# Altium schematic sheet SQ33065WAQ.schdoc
size 127 x 101 mm
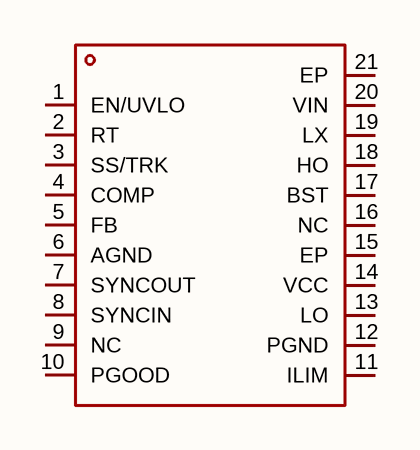
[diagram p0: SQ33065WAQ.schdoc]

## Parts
U?  sq33065waq  [TQFN-20_L4.5-W3.5-P0.50-TL-EP2.7]  (value not drawn)

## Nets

Not connected (* = marked no-connect by the designer): U? 1(EN/UVLO) 2(RT) 3(SS/TRK) 4(COMP) 5(FB) 6(AGND) 7(SYNCOUT) 8(SYNCIN) 9(NC) 10(PGOOD) 11(ILIM) 12(PGND) 13(LO) 14(VCC) 15(EP) 16(NC) 17(BST) 18(HO) 19(LX) 20(VIN) 21(EP)

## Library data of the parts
U? = sq33065waq: 功能类型:降压型;工作电压:6V~75V;输出电压:-;输出电流:-;输出类型:可调;; Manufacturer: Silergy(矽力杰); AddInBom: yes; ModelId: 6dcfd1dce8a14f26a8edd1e12c18b7a2; ModelTransform: 137.795,177.165,0,0,0,0,0,0,0; Function: 降压型; Voltage - Supply: 6V~75V; Frequency - Switching: 100kHz~1MHz; Synchronous Rectifier: 是; Number of Outputs: 1; Topology: 降压式; Quiescent Current: 1mA; Switch tube (built-in/external): 外置; Output Type: 可调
